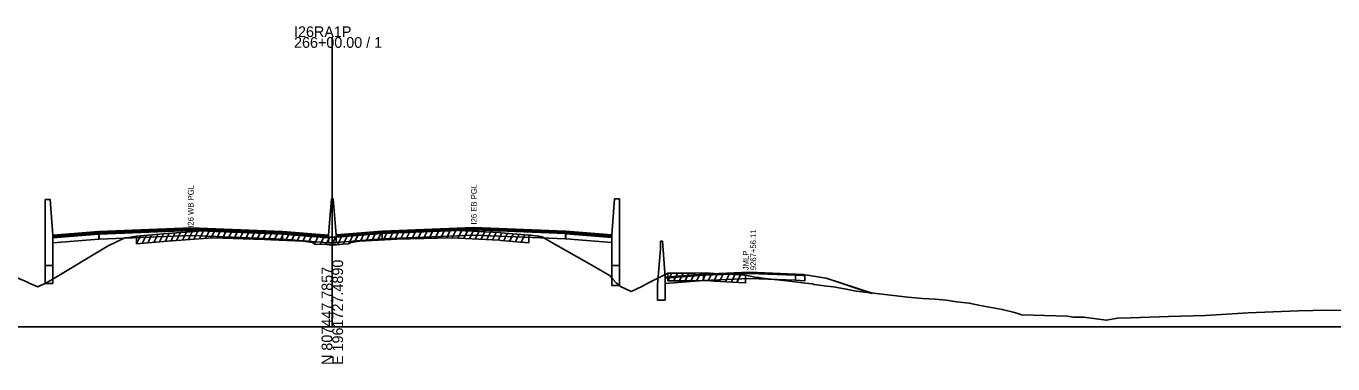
# Model space of a CAD drawing. Extents: x 1017 to 19997, y -1947 to 50737.
# Drawn here: x 10520 to 10861.4, y 15990.3 to 16078.4 of the extents above; entities that cross this region are included whole.
import ezdxf

# ---------------------------------------------------------------- set-up
doc = ezdxf.new("R2010")
doc.units = 0
for name, color, linetype in [('RD_GPK_XS_Cell', 7, 'Continuous'), ('RD_XS_Base', 7, 'Continuous'), ('RD_XS_ExGround', 7, 'Continuous'), ('RD_XS_ExPaveRet', 7, 'Continuous'), ('RD_XS_Greenside', 7, 'Continuous'), ('RD_XS_MedBWall', 7, 'Continuous'), ('RD_XS_Pave', 7, 'Continuous'), ('RD_XS_PaveOvlay', 7, 'Continuous'), ('RD_XS_TieSlope', 7, 'Continuous'), ('RD_XS_TX_Notes', 7, 'Continuous')]:
    doc.layers.add(name, color=color, linetype=linetype)

msp = doc.modelspace()

# ---------------------------------------------------------------- linework, layer by layer
at = {"layer": 'RD_GPK_XS_Cell'}
for p, q in [((10600, 16000), (10600, 16075.55)), ((10000, 16000), (10600, 16000)), ((10600, 16000), (11200, 16000))]:
    msp.add_line(p, q, dxfattribs=at)
at = {"layer": 'RD_XS_Base'}
for points in [[(10539, 16024.16), (10527, 16023.2)], [(10527, 16023.2), (10527, 16021.86)], [(10539, 16022.82), (10539, 16024.16)], [(10539.05, 16024.16), (10539.05, 16022.82)], [(10539.05, 16022.82), (10563, 16023.79), (10587, 16022.82)], [(10587, 16022.82), (10587, 16024.16)], [(10599, 16023.22), (10587, 16024.16)], [(10599, 16021.88), (10599, 16023.22)], [(10601, 16021.99), (10601, 16023.33)], [(10613, 16022.93), (10601, 16021.99)], [(10613, 16022.93), (10613, 16024.27)], [(10660.95, 16022.93), (10637, 16023.9), (10613, 16022.93)], [(10660.95, 16022.93), (10660.95, 16024.27)], [(10661, 16022.93), (10660.95, 16022.93)], [(10661, 16024.27), (10661, 16022.93)], [(10661, 16024.26), (10673, 16023.3)], [(10661, 16022.92), (10661, 16024.26)], [(10673, 16021.96), (10661, 16022.92)], [(10673, 16023.3), (10673, 16021.96)], [(10527, 16021.86), (10539, 16022.82)], [(10539.05, 16022.82), (10539, 16022.82)], [(10587, 16022.82), (10599, 16021.88)], [(10697, 16013.42), (10687, 16012.62)], [(10687, 16012.62), (10687, 16011.28)], [(10697, 16013.42), (10709, 16013.9), (10721, 16013.42)], [(10697, 16012.08), (10697, 16013.42)], [(10721, 16013.42), (10721, 16012.1)], [(10721, 16013.42), (10723, 16013.34), (10723.5, 16013.32)], [(10723.5, 16013.32), (10723.5, 16011.98)], [(10687, 16011.28), (10697, 16012.08)], [(10721, 16012.1), (10709, 16012.56), (10697, 16012.08)], [(10723.5, 16011.98), (10721, 16012.1)]]:
    msp.add_lwpolyline(points, dxfattribs=at)
at = {"layer": 'RD_XS_ExGround'}
msp.add_lwpolyline([(10513.04, 16014.69), (10520.32, 16011.59), (10520.76, 16011.39), (10523.02, 16010.4), (10525.27, 16011.4), (10525.58, 16011.63), (10526.36, 16012.02), (10541.44, 16021.07), (10545.82, 16023.19), (10546.82, 16023.3), (10547.37, 16023.39), (10548.83, 16023.57), (10556.9, 16024.27), (10568.66, 16025.16), (10579.42, 16024.86), (10580.43, 16024.83), (10584.04, 16024.67), (10592.34, 16024.3), (10594.25, 16024.06), (10594.84, 16023.97), (10595.41, 16023.55), (10598.44, 16023.4), (10599.19, 16023.39), (10600, 16023.38), (10601.13, 16023.37), (10602.85, 16023.51), (10604.24, 16023.61), (10604.42, 16023.73), (10604.64, 16023.75), (10604.87, 16024), (10607.15, 16024.29), (10618.55, 16024.89), (10619.42, 16024.94), (10620.31, 16024.95), (10631.16, 16025.18), (10641.81, 16024.63), (10643.69, 16024.53), (10644.05, 16024.5), (10651.37, 16023.91), (10651.88, 16023.85), (10653.54, 16023.64), (10653.96, 16023.58), (10654.81, 16023.44), (10657.21, 16022.01), (10667.77, 16016.03), (10672.57, 16013.26), (10673.3, 16012.39), (10674.12, 16011.45), (10675.29, 16010.45), (10678.04, 16009.14), (10680.86, 16010.44), (10682.99, 16011.57), (10687.69, 16013.95), (10694.85, 16013.96), (10697.74, 16014.01), (10699.78, 16013.84), (10707.84, 16013.43), (10708.73, 16013.22), (10710.86, 16012.83), (10711.52, 16012.79), (10712.3, 16012.69), (10719.46, 16011.87), (10720.09, 16011.75), (10722.29, 16011.54), (10722.88, 16011.41), (10725.36, 16011.17), (10725.89, 16011.03), (10729.24, 16010.54), (10730.95, 16010.37), (10734.29, 16009.79), (10736.91, 16009.27), (10750.38, 16007.73), (10754.2, 16007.34), (10757.5, 16007.21), (10760.51, 16006.91), (10763.1, 16006.48), (10766.43, 16006.14), (10769.3, 16005.54), (10775.03, 16004.48), (10777.87, 16003.79), (10779.12, 16003.45), (10780.05, 16003.09), (10792.05, 16002.77), (10793.6, 16002.51), (10796.32, 16002.52), (10802.21, 16001.67), (10805.21, 16002.23), (10808.59, 16002.3), (10818.5, 16002.65), (10828.15, 16002.95), (10839.33, 16003.63), (10852.39, 16004.17), (10860.09, 16004.29), (10868.9, 16004.26)], dxfattribs=at)
at = {"layer": 'RD_XS_ExPaveRet'}
for p, q in [((10548.83, 16021.57), (10549.88, 16023.66)), ((10548.83, 16021.57), (10548.83, 16023.57)), ((10550.33, 16021.7), (10551.38, 16023.79)), ((10551.83, 16021.83), (10552.88, 16023.92)), ((10553.33, 16021.96), (10554.38, 16024.05)), ((10554.83, 16022.09), (10555.88, 16024.18)), ((10556.33, 16022.22), (10557.38, 16024.3)), ((10556.9, 16022.27), (10568.66, 16023.16)), ((10557.83, 16022.34), (10558.87, 16024.42)), ((10559.33, 16022.45), (10560.37, 16024.53)), ((10560.83, 16022.57), (10561.87, 16024.65)), ((10562.33, 16022.68), (10563.37, 16024.76)), ((10563.83, 16022.8), (10564.87, 16024.88)), ((10565.33, 16022.91), (10566.37, 16024.99)), ((10566.83, 16023.02), (10567.87, 16025.1)), ((10568.33, 16023.14), (10569.34, 16025.14)), ((10568.66, 16023.16), (10579.42, 16022.86)), ((10569.83, 16023.13), (10570.82, 16025.1)), ((10571.33, 16023.09), (10572.32, 16025.06)), ((10572.83, 16023.05), (10573.82, 16025.02)), ((10574.33, 16023), (10575.32, 16024.97)), ((10575.83, 16022.96), (10576.82, 16024.93)), ((10577.33, 16022.92), (10578.32, 16024.89)), ((10578.83, 16022.87), (10579.82, 16024.85)), ((10579.42, 16022.86), (10580.43, 16022.83)), ((10580.33, 16022.83), (10581.31, 16024.79)), ((10581.83, 16022.76), (10582.81, 16024.72)), ((10583.33, 16022.7), (10584.31, 16024.65)), ((10584.83, 16022.63), (10585.81, 16024.59)), ((10586.33, 16022.56), (10587.31, 16024.52)), ((10587.83, 16022.5), (10588.81, 16024.45)), ((10589.33, 16022.43), (10590.31, 16024.39)), ((10590.83, 16022.36), (10591.81, 16024.32)), ((10592.33, 16022.3), (10593.28, 16024.18)), ((10593.83, 16022.11), (10594.77, 16023.98)), ((10595.33, 16021.61), (10596.29, 16023.51)), ((10596.83, 16021.48), (10597.81, 16023.43)), ((10598.33, 16021.4), (10599.33, 16023.39)), ((10599.83, 16021.38), (10600.83, 16023.37)), ((10601.33, 16021.38), (10602.38, 16023.47)), ((10602.83, 16021.51), (10603.87, 16023.58)), ((10604.33, 16021.67), (10605.54, 16024.09)), ((10605.83, 16022.12), (10606.9, 16024.26)), ((10607.15, 16022.29), (10618.55, 16022.89)), ((10607.33, 16022.3), (10608.36, 16024.36)), ((10608.83, 16022.38), (10609.86, 16024.43)), ((10610.33, 16022.46), (10611.36, 16024.51)), ((10611.83, 16022.54), (10612.86, 16024.59)), ((10613.33, 16022.61), (10614.36, 16024.67)), ((10614.83, 16022.69), (10615.86, 16024.75)), ((10616.33, 16022.77), (10617.36, 16024.82)), ((10617.83, 16022.85), (10618.86, 16024.9)), ((10618.55, 16022.89), (10619.42, 16022.94)), ((10619.33, 16022.93), (10620.35, 16024.96)), ((10619.42, 16022.94), (10620.31, 16022.95)), ((10620.31, 16022.95), (10631.16, 16023.18)), ((10620.83, 16022.97), (10621.85, 16024.99)), ((10622.33, 16023), (10623.35, 16025.02)), ((10623.83, 16023.03), (10624.85, 16025.05)), ((10625.33, 16023.06), (10626.35, 16025.08)), ((10626.83, 16023.09), (10627.85, 16025.11)), ((10628.33, 16023.12), (10629.35, 16025.15)), ((10629.83, 16023.16), (10630.85, 16025.18)), ((10631.16, 16023.18), (10641.81, 16022.63)), ((10631.33, 16023.18), (10632.31, 16025.12)), ((10632.83, 16023.1), (10633.81, 16025.05)), ((10634.33, 16023.02), (10635.31, 16024.97)), ((10635.83, 16022.94), (10636.81, 16024.89)), ((10637.33, 16022.86), (10638.31, 16024.81)), ((10638.83, 16022.78), (10639.81, 16024.73)), ((10640.33, 16022.7), (10641.31, 16024.65)), ((10641.83, 16022.63), (10642.81, 16024.58)), ((10643.33, 16022.55), (10644.3, 16024.48)), ((10644.83, 16022.44), (10645.8, 16024.36)), ((10646.33, 16022.32), (10647.3, 16024.24)), ((10647.83, 16022.2), (10648.8, 16024.12)), ((10649.33, 16022.08), (10650.3, 16024)), ((10651.37, 16023.91), (10651.37, 16021.91)), ((10548.83, 16021.57), (10556.9, 16022.27)), ((10580.43, 16022.83), (10584.04, 16022.67)), ((10584.04, 16022.67), (10592.34, 16022.3)), ((10592.34, 16022.3), (10594.25, 16022.06)), ((10594.25, 16022.06), (10594.84, 16021.97)), ((10594.84, 16021.97), (10595.41, 16021.55)), ((10595.41, 16021.55), (10598.44, 16021.4)), ((10598.44, 16021.4), (10599.19, 16021.39)), ((10599.19, 16021.39), (10600, 16021.38)), ((10600, 16021.38), (10601.13, 16021.37)), ((10601.13, 16021.37), (10602.85, 16021.51)), ((10602.85, 16021.51), (10604.24, 16021.61)), ((10604.24, 16021.61), (10604.42, 16021.73)), ((10604.42, 16021.73), (10604.64, 16021.75)), ((10604.64, 16021.75), (10604.87, 16022)), ((10604.87, 16022), (10607.15, 16022.29)), ((10641.81, 16022.63), (10643.69, 16022.53)), ((10643.69, 16022.53), (10644.05, 16022.5)), ((10644.05, 16022.5), (10651.37, 16021.91)), ((10687.69, 16011.95), (10688.69, 16013.95)), ((10687.69, 16011.95), (10687.69, 16013.95)), ((10689.19, 16011.95), (10690.19, 16013.95)), ((10690.69, 16011.95), (10691.69, 16013.95)), ((10692.19, 16011.95), (10693.19, 16013.96)), ((10693.69, 16011.96), (10694.69, 16013.96)), ((10695.19, 16011.96), (10696.19, 16013.98)), ((10696.69, 16011.99), (10697.69, 16014.01)), ((10698.19, 16011.97), (10699.15, 16013.89)), ((10699.69, 16011.84), (10700.66, 16013.79)), ((10701.19, 16011.76), (10702.16, 16013.71)), ((10702.69, 16011.69), (10703.66, 16013.64)), ((10704.19, 16011.61), (10705.16, 16013.56)), ((10705.69, 16011.53), (10706.66, 16013.49)), ((10707.97, 16013.39), (10707.97, 16011.39)), ((10687.69, 16011.95), (10694.85, 16011.96)), ((10694.85, 16011.96), (10697.74, 16012.01)), ((10697.74, 16012.01), (10699.78, 16011.84)), ((10699.78, 16011.84), (10707.84, 16011.43)), ((10707.84, 16011.43), (10707.97, 16011.39))]:
    msp.add_line(p, q, dxfattribs=at)
at = {"layer": 'RD_XS_Greenside'}
for points in [[(10723, 16013.65), (10729, 16012.69)], [(10729, 16012.69), (10741, 16008.69)], [(10729, 16012.69), (10741.05, 16008.74)]]:
    msp.add_lwpolyline(points, dxfattribs=at)
at = {"layer": 'RD_XS_MedBWall'}
for points in [[(10527, 16023.88), (10526.25, 16033.22), (10525, 16033.22)], [(10525, 16033.22), (10525, 16016)], [(10525, 16011.28), (10525, 16033.22)], [(10599, 16023.88), (10599.75, 16033.32), (10600.25, 16033.32), (10601, 16023.99)], [(10675, 16033.32), (10673.75, 16033.32), (10673, 16023.98)], [(10675, 16016), (10675, 16033.32)], [(10675, 16010.7), (10675, 16033.32)], [(10527, 16016), (10527, 16023.88)], [(10527, 16023.88), (10527, 16011.28)], [(10599, 16021.88), (10599, 16023.88)], [(10601, 16023.99), (10601, 16021.88)], [(10673, 16023.98), (10673, 16016)], [(10673, 16023.98), (10673, 16010.7)], [(10601, 16021.88), (10599, 16021.88)], [(10685.75, 16020.27), (10685, 16010.93)], [(10687, 16012.93), (10686.25, 16022.27), (10685.75, 16022.27)], [(10685.75, 16022.27), (10685.75, 16020.27)], [(10525, 16016), (10527, 16016)], [(10673, 16016), (10675, 16016)], [(10687, 16006.93), (10687, 16012.93)], [(10527, 16011.28), (10525, 16011.28)], [(10673, 16010.7), (10675, 16010.7)], [(10685, 16010.93), (10685, 16006.93)], [(10685, 16006.93), (10687, 16006.93)]]:
    msp.add_lwpolyline(points, dxfattribs=at)
at = {"layer": 'RD_XS_Pave'}
for points in [[(10539, 16024.5), (10527, 16023.54)], [(10527, 16023.54), (10527, 16023.2)], [(10539, 16024.16), (10539, 16024.5)], [(10539.05, 16024.16), (10539, 16024.16)], [(10539.05, 16024.5), (10563, 16025.46), (10587, 16024.5)], [(10587, 16024.16), (10563, 16025.13), (10539.05, 16024.16)], [(10539.05, 16024.16), (10539.05, 16024.5)], [(10587, 16024.5), (10587, 16024.16)], [(10587, 16024.5), (10599, 16023.56)], [(10599, 16023.56), (10599, 16023.22)], [(10613, 16024.61), (10601, 16023.67)], [(10601, 16023.33), (10613, 16024.27)], [(10601, 16023.67), (10601, 16023.33)], [(10660.95, 16024.61), (10637, 16025.57), (10613, 16024.61)], [(10613, 16024.27), (10637, 16025.24), (10660.95, 16024.27)], [(10613, 16024.61), (10613, 16024.27)], [(10660.95, 16024.27), (10660.95, 16024.61)], [(10660.95, 16024.61), (10661, 16024.61)], [(10661, 16024.27), (10660.95, 16024.27)], [(10661, 16024.61), (10661, 16024.27)], [(10661, 16024.26), (10661, 16024.6)], [(10673, 16023.64), (10673, 16023.3)]]:
    msp.add_lwpolyline(points, dxfattribs=at)
at = {"layer": 'RD_XS_PaveOvlay'}
for points in [[(10539, 16024.84), (10527, 16023.88)], [(10527, 16023.88), (10527, 16023.54)], [(10539.05, 16024.84), (10539, 16024.84)], [(10539, 16024.84), (10539, 16024.5)], [(10539, 16024.5), (10539.05, 16024.5)], [(10539.05, 16024.84), (10563, 16025.8), (10587, 16024.84)], [(10539.05, 16024.5), (10539.05, 16024.84)], [(10587, 16024.84), (10587, 16024.5)], [(10587, 16024.84), (10599, 16023.88)], [(10599, 16023.88), (10599, 16023.56)], [(10613, 16024.94), (10601, 16023.99)], [(10601, 16023.99), (10601, 16023.67)], [(10660.95, 16024.95), (10637, 16025.91), (10613, 16024.94)], [(10613, 16024.94), (10613, 16024.61)], [(10660.95, 16024.61), (10660.95, 16024.95)], [(10660.95, 16024.95), (10661, 16024.94)], [(10661, 16024.94), (10661, 16024.61)], [(10661, 16024.94), (10673, 16023.98)], [(10661, 16024.6), (10661, 16024.94)], [(10673, 16023.64), (10661, 16024.6)], [(10673, 16023.98), (10673, 16023.64)], [(10697, 16013.73), (10687, 16012.93)], [(10687, 16012.62), (10697, 16013.42)], [(10687, 16012.93), (10687, 16012.62)], [(10697, 16013.73), (10709, 16014.21), (10721, 16013.73)], [(10721, 16013.42), (10709, 16013.9), (10697, 16013.42)], [(10697, 16013.42), (10697, 16013.73)], [(10721, 16013.73), (10721, 16013.42)], [(10721, 16013.73), (10723, 16013.65)], [(10723, 16013.34), (10721, 16013.42)], [(10723, 16013.65), (10723, 16013.34)]]:
    msp.add_lwpolyline(points, dxfattribs=at)
at = {"layer": 'RD_XS_TieSlope'}
msp.add_lwpolyline([(10741, 16008.69), (10741.05, 16008.74)], dxfattribs=at)

# ---------------------------------------------------------------- texts
at = {"layer": 'RD_GPK_XS_Cell'}
for s, p in [('I26RA1P', (10590, 16075.55)), ('266+00.00 / 1', (10590, 16072.75))]:
    msp.add_text(s, height=2.8, dxfattribs=at).set_placement(p)
for s, p in [('E 1961727.4890', (10602.8, 15990)), ('N 807447.7857', (10600, 15990))]:
    msp.add_text(s, height=2.8, rotation=90, dxfattribs=at).set_placement(p)
at = {"layer": 'RD_XS_TX_Notes'}
for s, p in [('I26 WB PGL', (10563.75, 16025.8)), ('I26 EB PGL', (10637.75, 16026.64)), (' 9267+56.11', (10710.73, 16014.17)), (' JMLP', (10708.77, 16014.17))]:
    msp.add_text(s, height=1.5, rotation=90, dxfattribs=at).set_placement(p)

doc.saveas('drawing.dxf')
